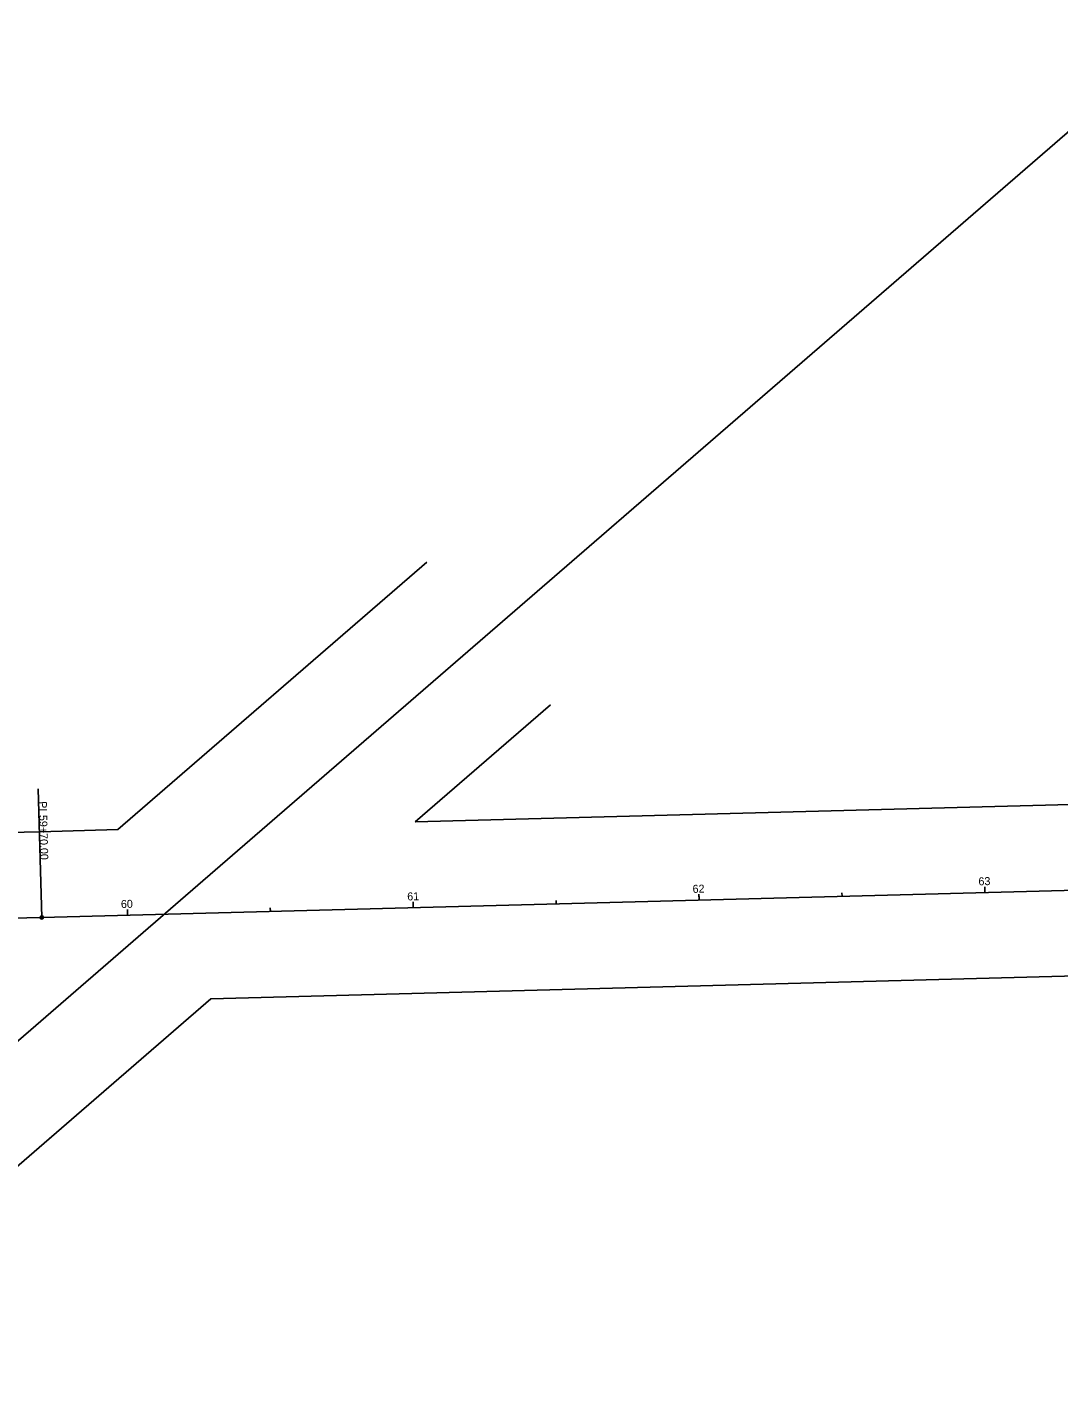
# Model space of a CAD drawing. Extents: x 2402033 to 2407434, y 498266 to 500417.
# Drawn here: x 2402999.4 to 2403360.2, y 498503.3 to 498977.4 of the extents above; entities that cross this region are included whole.
import ezdxf

# ---------------------------------------------------------------- set-up
doc = ezdxf.new("R2010")
doc.units = 0
for name, color, linetype in [('DR_P_Ditch', 7, 'Continuous'), ('GK_Drainage_Nodes', 7, 'Continuous'), ('PV_P_EOP', 7, 'Continuous'), ('PV_P_Shoulder', 7, 'Continuous'), ('RD_P_GR_Lt', 7, 'Continuous'), ('RD_P_GR_Rt', 7, 'Continuous'), ('RD_X_RR_Cells', 7, 'Continuous'), ('SN_X_Public', 7, 'Continuous'), ('UT_X_Electric_Cells', 7, 'Continuous')]:
    doc.layers.add(name, color=color, linetype=linetype)

msp = doc.modelspace()

# ---------------------------------------------------------------- linework, layer by layer
at = {"layer": 'DR_P_Ditch'}
msp.add_line((2403004.47, 498665.82), (2403003.28, 498710.8), dxfattribs=at)
msp.add_circle((2403004.47, 498665.82), 0.6, dxfattribs=at)
at = {"layer": 'GK_Drainage_Nodes'}
msp.add_line((2403004.47, 498665.82), (2403003.28, 498710.8), dxfattribs=at)
msp.add_circle((2403004.47, 498665.82), 0.6, dxfattribs=at)
at = {"layer": 'PV_P_EOP'}
for p, q in [((2403004.47, 498665.82), (2407431.7, 498783.04)), ((2402034.69, 498645.41), (2403004.47, 498665.82))]:
    msp.add_line(p, q, dxfattribs=at)
msp.add_lwpolyline([(2402858.39, 498503.28), (2403052.97, 498671.81), (2404213.72, 499677.16)], dxfattribs=at)
at = {"layer": 'PV_P_Shoulder'}
for p, q in [((2403234.39, 498671.91), (2403234.36, 498673.11)), ((2403334.36, 498674.55), (2403334.33, 498675.75)), ((2403034.46, 498666.61), (2403034.41, 498668.61)), ((2403134.43, 498669.26), (2403134.4, 498670.46))]:
    msp.add_line(p, q, dxfattribs=at)
at = {"layer": 'RD_P_GR_Lt'}
for p, q in [((2403334.36, 498674.55), (2403334.3, 498676.55)), ((2403134.43, 498669.26), (2403134.37, 498671.26)), ((2403184.41, 498670.58), (2403184.38, 498671.78)), ((2403234.39, 498671.91), (2403234.34, 498673.91)), ((2403284.38, 498673.23), (2403284.34, 498674.43)), ((2403034.46, 498666.61), (2403034.41, 498668.61)), ((2403084.45, 498667.94), (2403084.41, 498669.14))]:
    msp.add_line(p, q, dxfattribs=at)
at = {"layer": 'RD_P_GR_Rt'}
msp.add_line((2403004.47, 498665.82), (2403003.28, 498710.8), dxfattribs=at)
msp.add_circle((2403004.47, 498665.82), 0.6, dxfattribs=at)
at = {"layer": 'RD_X_RR_Cells'}
for p, q in [((2403031.12, 498696.54), (2403139.14, 498790.1)), ((2403135.11, 498699.29), (2403182.35, 498740.21)), ((2402955.58, 498543.8), (2403063.62, 498637.38))]:
    msp.add_line(p, q, dxfattribs=at)
at = {"layer": 'SN_X_Public'}
msp.add_line((2403034.46, 498666.61), (2403034.41, 498668.61), dxfattribs=at)
at = {"layer": 'UT_X_Electric_Cells'}
msp.add_line((2403063.62, 498637.38), (2404534.73, 498676.32), dxfattribs=at)
for points in [[(2403135.11, 498699.29), (2404206.24, 498727.65), (2404204.58, 498797.57)], [(2402234.01, 498679.61), (2403003.76, 498695.81), (2403031.12, 498696.54)]]:
    msp.add_lwpolyline(points, dxfattribs=at)

# ---------------------------------------------------------------- texts
at = {"layer": 'DR_P_Ditch'}
for s, p in [('PI', (2403003.44, 498706.43)), ('59+70.00', (2403003.57, 498701.64))]:
    msp.add_text(s, height=2.8, rotation=271.5166, dxfattribs=at).set_placement(p)
at = {"layer": 'GK_Drainage_Nodes'}
for s, p in [('PI', (2403003.44, 498706.43)), ('59+70.00', (2403003.57, 498701.64))]:
    msp.add_text(s, height=2.8, rotation=271.5166, dxfattribs=at).set_placement(p)
at = {"layer": 'PV_P_Shoulder'}
msp.add_text('60', height=2.8, rotation=1.5166, dxfattribs=at).set_placement((2403032.2, 498669.1))
at = {"layer": 'RD_P_GR_Lt'}
for s, p in [('62', (2403232.14, 498674.4)), ('63', (2403332.11, 498677.04)), ('60', (2403032.2, 498669.1)), ('61', (2403132.34, 498671.75))]:
    msp.add_text(s, height=2.8, rotation=1.5166, dxfattribs=at).set_placement(p)
at = {"layer": 'RD_P_GR_Rt'}
for s, p in [('PI', (2403003.44, 498706.43)), ('59+70.00', (2403003.57, 498701.64))]:
    msp.add_text(s, height=2.8, rotation=271.5166, dxfattribs=at).set_placement(p)
at = {"layer": 'SN_X_Public'}
msp.add_text('60', height=2.8, rotation=1.5166, dxfattribs=at).set_placement((2403032.2, 498669.1))

doc.saveas('drawing.dxf')
